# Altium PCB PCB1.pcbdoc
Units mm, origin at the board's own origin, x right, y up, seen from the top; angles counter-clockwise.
Board outline 149.48 x 93.01 mm, 2 copper layers (Top Layer, Bottom Layer); 121 components, 55 nets, 274 pads, 98 vias.
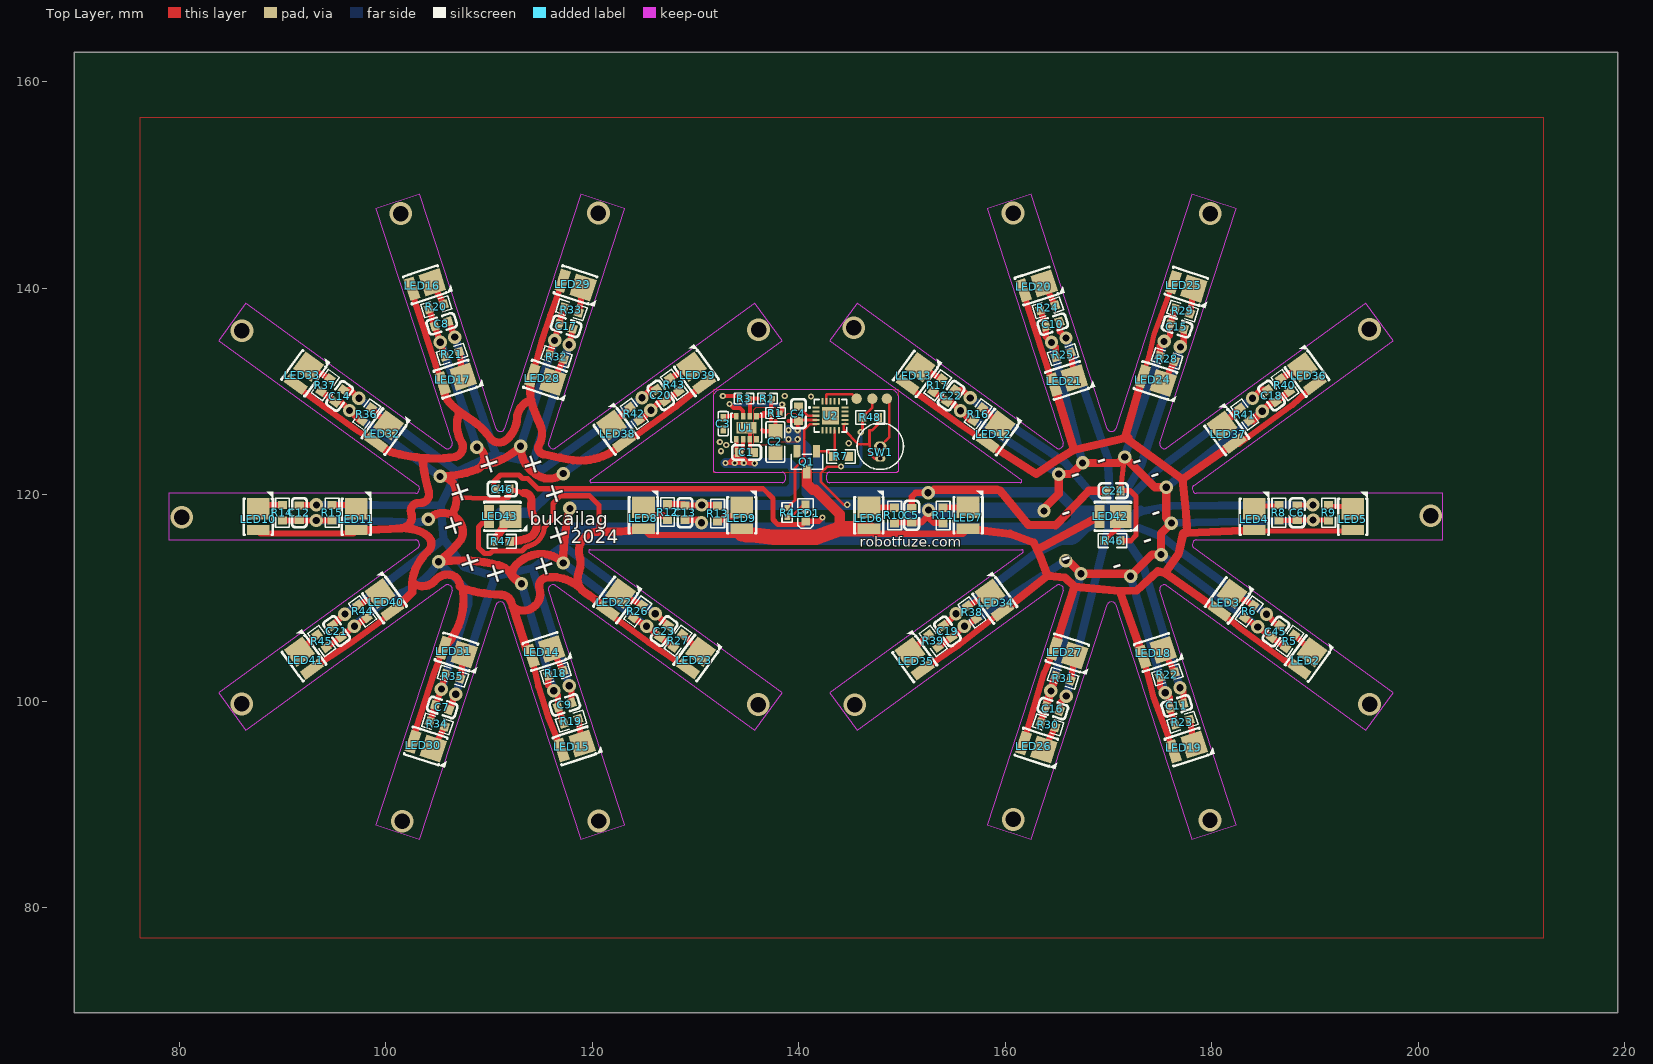
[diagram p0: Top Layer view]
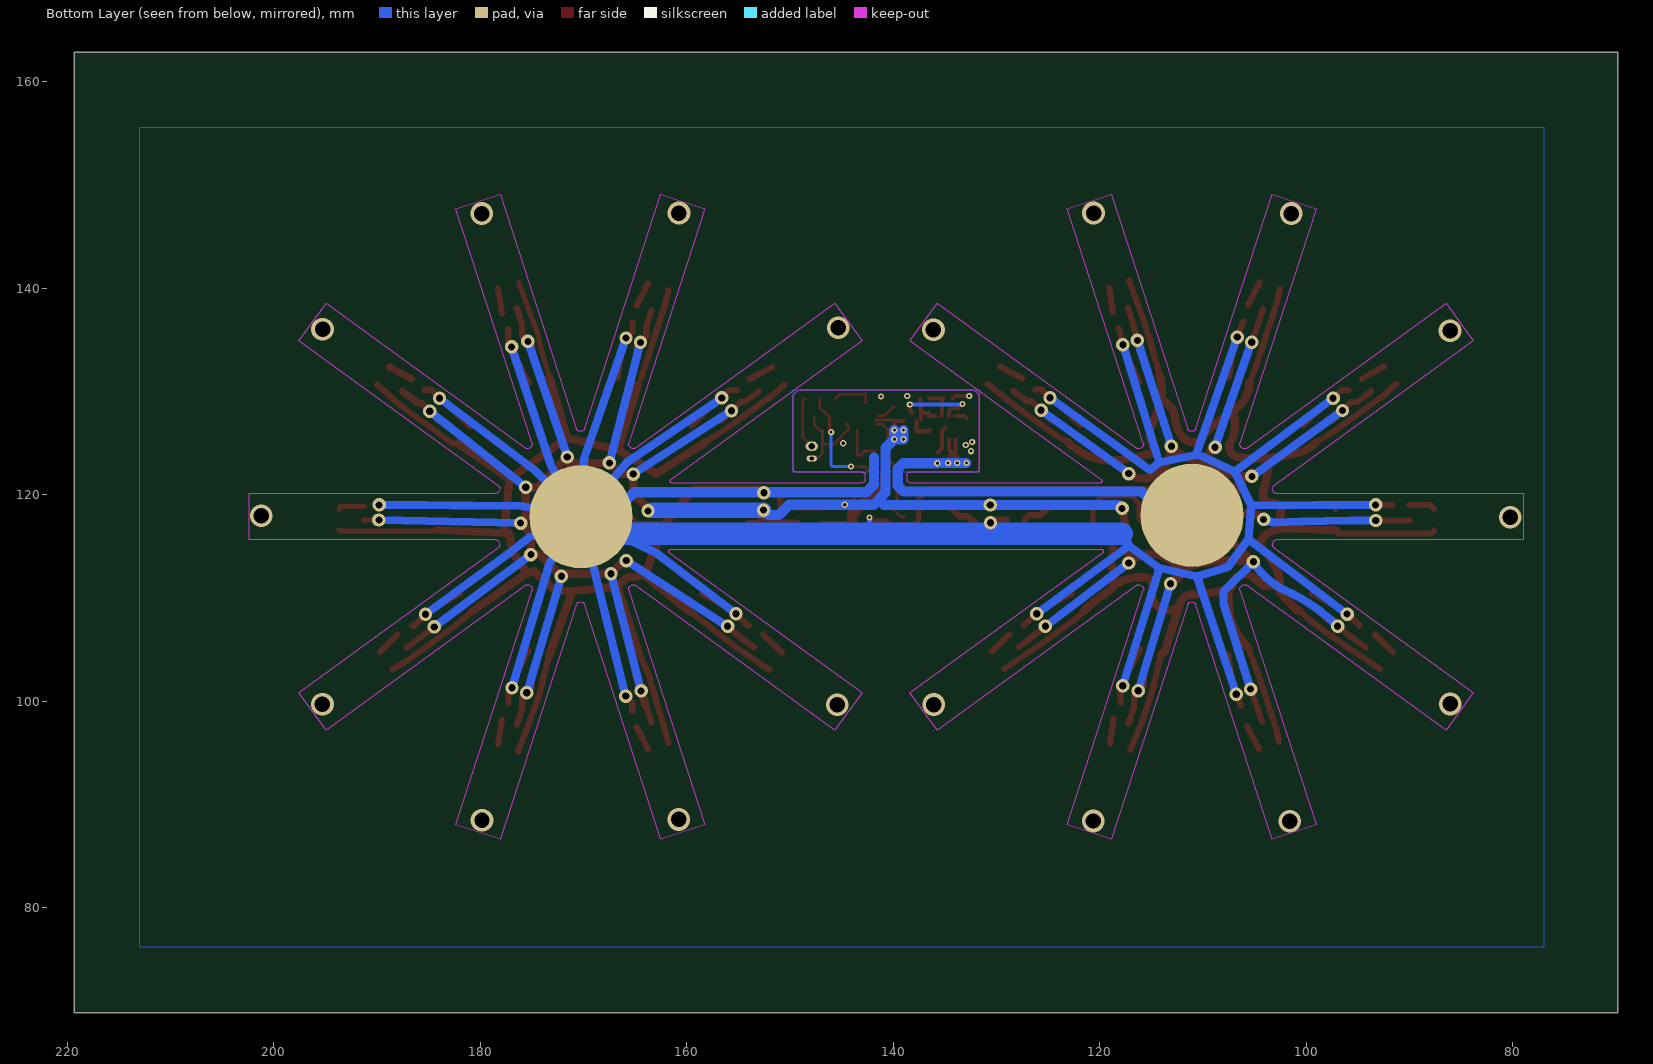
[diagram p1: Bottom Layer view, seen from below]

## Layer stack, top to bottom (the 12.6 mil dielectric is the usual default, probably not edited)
Top Layer: signal copper (thickness not stored)
Dielectric: dielectric 0.32, FR-4, Dk 4.8
Bottom Layer: signal copper (thickness not stored)

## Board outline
219.326,69.85 69.85,69.85 69.85,162.858 219.326,162.858

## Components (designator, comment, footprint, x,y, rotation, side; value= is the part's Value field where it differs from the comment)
C1 "GRM188R60J226MEA0D" C0603 134.95,124.111 r180 top
C2 "GRM21BR60J226ME39L" C0805 137.744,125.127 r90 top
C3 "430pF" C0402 132.702,126.905 r90 top
C4 "GRM188R60J226MEA0D" C0603 139.987,127.861 r270 top
C5 "GRM188R60J226MEA0D" C0603 150.952,118.015 r270 top
C6 "GRM188R60J226MEA0D" C0603 188.29,118.269 r270 top
C7 "GRM188R60J226MEA0D" C0603 105.475,99.41 r162 top
C8 "GRM188R60J226MEA0D" C0603 105.41,136.569 r198 top
C9 "GRM188R60J226MEA0D" C0603 117.348,99.651 r198 top
C10 "GRM188R60J226MEA0D" C0603 164.605,136.531 r198 top
C11 "GRM188R60J226MEA0D" C0603 176.606,99.562 r198 top
C12 "GRM188R60J226MEA0D" C0603 91.643,118.269 r270 top
C13 "GRM188R60J226MEA0D" C0603 128.994,118.281 r90 top
C14 "GRM188R60J226MEA0D" C0603 95.529,129.572 r234 top
C15 "GRM188R60J226MEA0D" C0603 176.644,136.29 r162 top
C16 "GRM188R60J226MEA0D" C0603 164.617,99.308 r162 top
C17 "GRM188R60J226MEA0D" C0603 117.471,136.327 r162 top
C18 "GRM188R60J226MEA0D" C0603 185.814,129.61 r306 top
C19 "GRM188R60J226MEA0D" C0603 154.419,106.775 r306 top
C20 "GRM188R60J226MEA0D" C0603 126.644,129.635 r306 top
C21 "GRM188R60J226MEA0D" C0603 95.25,106.801 r306 top
C22 "GRM188R60J226MEA0D" C0603 154.762,129.597 r234 top
C23 "GRM188R60J226MEA0D" C0603 126.962,106.801 r234 top
C24 "GRM188R60J226MEA0D" C0603 170.485,120.402 r0 top
C45 "GRM188R60J226MEA0D" C0603 186.22,106.763 r234 top
C46 "GRM188R60J226MEA0D" C0603 111.303,120.567 r0 top
LED1 "MHT192CRCT" LED0603-RD 140.678,118.243 r90 top
LED2 "L128-4080CB3500001_C358168" LED-SMD_L128-XX80CB3500001 189.118,103.931 r54 top
LED3 "L128-4080CB3500001_C358168" LED-SMD_L128-XX80CB3500001 181.371,109.572 r54 top
LED4 "L128-4080CB3500001_C358168" LED-SMD_L128-XX80CB3500001 184.142,117.628 r90 top
LED5 "L128-4080CB3500001_C358168" LED-SMD_L128-XX80CB3500001 193.665,117.628 r90 top
LED6 "L128-4080CB3500001_C358168" LED-SMD_L128-XX80CB3500001 146.808,117.755 r90 top
LED7 "L128-4080CB3500001_C358168" LED-SMD_L128-XX80CB3500001 156.413,117.761 r90 top
LED8 "L128-4080CB3500001_C358168" LED-SMD_L128-XX80CB3500001 124.968,117.755 r90 top
LED9 "L128-4080CB3500001_C358168" LED-SMD_L128-XX80CB3500001 134.491,117.755 r90 top
LED10 "L128-4080CB3500001_C358168" LED-SMD_L128-XX80CB3500001 87.662,117.628 r90 top
LED11 "L128-4080CB3500001_C358168" LED-SMD_L128-XX80CB3500001 97.157,117.628 r90 top
LED12 "L128-4080CB3500001_C358168" LED-SMD_L128-XX80CB3500001 158.912,125.876 r54 top
LED13 "L128-4080CB3500001_C358168" LED-SMD_L128-XX80CB3500001 151.152,131.517 r54 top
LED14 "L128-4080CB3500001_C358168" LED-SMD_L128-XX80CB3500001 115.113,104.743 r18 top
LED15 "L128-4080CB3500001_C358168" LED-SMD_L128-XX80CB3500001 118.034,95.612 r18 top
LED16 "L128-4080CB3500001_C358168" LED-SMD_L128-XX80CB3500001 103.54,140.27 r18 top
LED17 "L128-4080CB3500001_C358168" LED-SMD_L128-XX80CB3500001 106.511,131.128 r18 top
LED18 "L128-4080CB3500001_C358168" LED-SMD_L128-XX80CB3500001 174.342,104.655 r18 top
LED19 "L128-4080CB3500001_C358168" LED-SMD_L128-XX80CB3500001 177.314,95.488 r18 top
LED20 "L128-4080CB3500001_C358168" LED-SMD_L128-XX80CB3500001 162.785,140.145 r18 top
LED21 "L128-4080CB3500001_C358168" LED-SMD_L128-XX80CB3500001 165.732,131.006 r18 top
LED22 "L128-4080CB3500001_C358168" LED-SMD_L128-XX80CB3500001 122.118,109.608 r54 top
LED23 "L128-4080CB3500001_C358168" LED-SMD_L128-XX80CB3500001 129.883,103.981 r54 top
LED24 "L128-4080CB3500001_C358168" LED-SMD_L128-XX80CB3500001 174.315,131.156 r342 top
LED25 "L128-4080CB3500001_C358168" LED-SMD_L128-XX80CB3500001 177.299,140.289 r342 top
LED26 "L128-4080CB3500001_C358168" LED-SMD_L128-XX80CB3500001 162.77,95.642 r342 top
LED27 "L128-4080CB3500001_C358168" LED-SMD_L128-XX80CB3500001 165.768,104.763 r342 top
LED28 "L128-4080CB3500001_C358168" LED-SMD_L128-XX80CB3500001 115.183,131.275 r342 top
LED29 "L128-4080CB3500001_C358168" LED-SMD_L128-XX80CB3500001 118.13,140.421 r342 top
LED30 "L128-4080CB3500001_C358168" LED-SMD_L128-XX80CB3500001 103.632,95.764 r342 top
LED31 "L128-4080CB3500001_C358168" LED-SMD_L128-XX80CB3500001 106.611,104.869 r342 top
LED32 "L128-4080CB3500001_C358168" LED-SMD_L128-XX80CB3500001 99.675,125.914 r54 top
LED33 "L128-4080CB3500001_C358168" LED-SMD_L128-XX80CB3500001 91.902,131.568 r54 top
LED34 "L128-4080CB3500001_C358168" LED-SMD_L128-XX80CB3500001 159.149,109.566 r126 top
LED35 "L128-4080CB3500001_C358168" LED-SMD_L128-XX80CB3500001 151.402,103.903 r126 top
LED36 "L128-4080CB3500001_C358168" LED-SMD_L128-XX80CB3500001 189.395,131.528 r126 top
LED37 "L128-4080CB3500001_C358168" LED-SMD_L128-XX80CB3500001 181.628,125.858 r126 top
LED38 "L128-4080CB3500001_C358168" LED-SMD_L128-XX80CB3500001 122.479,125.927 r126 top
LED39 "L128-4080CB3500001_C358168" LED-SMD_L128-XX80CB3500001 130.251,131.578 r126 top
LED40 "L128-4080CB3500001_C358168" LED-SMD_L128-XX80CB3500001 100.051,109.607 r126 top
LED41 "L128-4080CB3500001_C358168" LED-SMD_L128-XX80CB3500001 92.245,103.968 r126 top
LED42 "L128-4080CB3500001_C358168" LED-SMD_L128-XX80CB3500001 170.18,117.913 r0 top
LED43 "L128-4080CB3500001_C358168" LED-SMD_L128-XX80CB3500001 111.052,117.912 r0 top
Q1 "AP3404" SOT-23-3_L2.9-W1.3-P1.90-LS2.4-BR-2 140.792,123.222 r180 top
R1 "CRCW0402100KFKED" R0402 137.744,127.921 r180 top
R2 "CRCW0402210KFKED" R0402 136.982,129.318 r0 top
R3 "CRCW0402100KFKED" R0402 134.709,129.318 r0 top
R4 "0402WGF1000TCE" R0402 138.887,118.292 r90 top
R5 "0603WAF100JT5E" R0603 187.592,105.835 r54 top
R6 "0603WAF100JT5E" R0603 183.642,108.706 r54 top
R7 "0603WAF100JT5E" R0603 144.094,123.73 r180 top
R8 "0603WAF100JT5E" R0603 186.512,118.269 r90 top
R9 "0603WAF100JT5E" R0603 191.338,118.269 r90 top
R10 "0603WAF100JT5E" R0603 149.301,118.015 r90 top
R11 "0603WAF100JT5E" R0603 154,118.015 r90 top
R12 "0603WAF100JT5E" R0603 127.305,118.332 r270 top
R13 "0603WAF100JT5E" R0603 132.156,118.193 r270 top
R14 "0603WAF100JT5E" R0603 89.992,118.269 r90 top
R15 "0603WAF100JT5E" R0603 94.818,118.269 r90 top
R16 "0603WAF100JT5E" R0603 157.378,127.806 r54 top
R17 "0603WAF100JT5E" R0603 153.466,130.615 r54 top
R18 "0603WAF100JT5E" R0603 116.472,102.711 r18 top
R19 "0603WAF100JT5E" R0603 117.958,98.076 r18 top
R20 "0603WAF100JT5E" R0603 104.902,138.22 r18 top
R21 "0603WAF100JT5E" R0603 106.413,133.623 r18 top
R22 "0603WAF100JT5E" R0603 175.717,102.572 r18 top
R23 "0603WAF100JT5E" R0603 177.178,97.987 r18 top
R24 "0603WAF100JT5E" R0603 164.134,138.113 r18 top
R25 "0603WAF100JT5E" R0603 165.621,133.56 r18 top
R26 "0603WAF100JT5E" R0603 124.422,108.706 r54 top
R27 "0603WAF100JT5E" R0603 128.321,105.874 r54 top
R28 "0603WAF100JT5E" R0603 175.692,133.204 r342 top
R29 "0603WAF100JT5E" R0603 177.19,137.814 r342 top
R30 "0603WAF100JT5E" R0603 164.158,97.725 r342 top
R31 "0603WAF100JT5E" R0603 165.621,102.241 r342 top
R32 "0603WAF100JT5E" R0603 116.548,133.382 r342 top
R33 "0603WAF100JT5E" R0603 117.996,137.916 r342 top
R34 "0603WAF100JT5E" R0603 105.004,97.809 r342 top
R35 "0603WAF100JT5E" R0603 106.512,102.431 r342 top
R36 "0603WAF100JT5E" R0603 98.171,127.794 r54 top
R37 "0603WAF100JT5E" R0603 94.17,130.639 r54 top
R38 "0603WAF100JT5E" R0603 156.794,108.617 r126 top
R39 "0603WAF100JT5E" R0603 153.043,105.846 r126 top
R40 "0603WAF100JT5E" R0603 187.109,130.639 r126 top
R41 "0603WAF100JT5E" R0603 183.197,127.781 r126 top
R42 "0603WAF100JT5E" R0603 124.092,127.845 r126 top
R43 "0603WAF100JT5E" R0603 127.953,130.677 r126 top
R44 "0603WAF100JT5E" R0603 97.76,108.713 r126 top
R45 "0603WAF100JT5E" R0603 93.802,105.835 r126 top
R46 "0603WAF100JT5E" R0603 170.409,115.564 r180 top
R47 "0603WAF100JT5E" R0603 111.252,115.5 r180 top
R48 "0603WAF100JT5E" R0603 146.93,127.507 r180 top
SW1 "SW-18010P" SW-TH_SW-18010P 147.904,124.111 r90 top
U1 "TPS82130SILR" USIP-8_L3.0-W2.8-P0.65-TL-EP 134.949,126.502 r90 top
U2 "ATTINY1616-MNR" QFN-20_L3.0-W3.0-P0.40-BL-EP1.7 143.093,127.665 r270 top

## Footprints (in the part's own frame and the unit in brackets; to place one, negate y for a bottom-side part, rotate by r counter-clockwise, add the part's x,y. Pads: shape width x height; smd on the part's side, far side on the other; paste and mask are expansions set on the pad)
C0402 [mm]
  rect 0.79x0.54 smd: 1(-0.545,0) 2(0.545,0)
  silkscreen extent -1.17,-0.5 1.17,0.5
C0603 [mm]
  rect 0.8x0.9 smd: 1(-0.7,0) 2(0.7,0)
  silkscreen extent -1.41,-0.71 1.39,0.72
C0805 [mm]
  rect 1.41x1.35 smd: 1(-1.03,0) 2(1.03,0)
  silkscreen extent -1.96,-0.9 1.96,0.9
LED0603-RD [mm]
  rect 0.8x0.8 smd: 1(-0.799,-0.003) 2(0.799,0.003)
  silkscreen extent -1.49,-0.75 1.39,0.76
LED-SMD_L128-XX80CB3500001 [mm]
  rect 1x2.2 smd: 1(-1.035,0)
  rect 2.1x2.2 smd: 2(1.035,0)
  silkscreen extent -1.49,-1.45 2.66,1.4
QFN-20_L3.0-W3.0-P0.40-BL-EP1.7 [mm]
  rect 0.2x0.665 smd: 1(-0.8,-1.407) 2(-0.4,-1.407) 3(0,-1.407) 4(0.4,-1.407) 5(0.8,-1.407) 11(0.8,1.407) 12(0.4,1.407) 13(0,1.407) 14(-0.4,1.407) 15(-0.8,1.407)
  rect 0.665x0.2 smd: 6(1.407,-0.8) 7(1.407,-0.4) 8(1.407,0) 9(1.407,0.4) 10(1.407,0.8) 16(-1.407,0.8) 17(-1.407,0.4) 18(-1.407,0) 19(-1.407,-0.4) 20(-1.407,-0.8)
  rect 1.65x1.65 smd: 21(0,0)
  silkscreen extent -1.58,-2.11 1.58,1.58
R0402 [mm]
  rect 0.566x0.54 smd: 1(-0.433,0) 2(0.433,0)
  silkscreen extent -0.94,-0.5 0.94,0.5
R0603 [mm]
  rect 0.806x0.864 smd: 1(-0.753,0) 2(0.753,0)
  silkscreen extent -1.39,-0.66 1.39,0.66
SOT-23-3_L2.9-W1.3-P1.90-LS2.4-BR-2 [mm]
  rect 0.7x1.25 smd: 1(0.95,-1) 2(-0.95,-1) 3(0,1)
  silkscreen extent -1.53,-0.73 1.53,0.73
SW-TH_SW-18010P [mm]
  oval 0.9x1.2 hole 0.6: 1(0.6,0)
  oval 0.6x1 hole 0.4: 2(-0.6,0)
  silkscreen extent -1.65,-2.25 2.85,2.25
USIP-8_L3.0-W2.8-P0.65-TL-EP [mm]
  rect 0.65x0.45 smd: 1(-1.125,0.975) 2(-1.125,0.325) 3(-1.125,-0.325) 4(-1.125,-0.975) 5(1.125,-0.975) 6(1.125,-0.325) 7(1.125,0.325) 8(1.125,0.975)
  rect 1.1x1.9 smd: 9(0,0)
  silkscreen extent -1.73,-1.5 1.4,1.5

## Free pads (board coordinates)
  round 1 smd: 4(145.618,129.318) 6(147.142,129.318) 7(148.539,129.318)
  round 10 smd far side: 5(111.074,118.015) 5(170.256,117.888)

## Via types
v1: diameter 1.3, hole 0.7, Top Layer to Bottom Layer, 59 vias
v2: diameter 0.61, hole 0.305, Top Layer to Bottom Layer, 21 vias
v3: diameter 2.2, hole 1.5, Top Layer to Bottom Layer, 18 vias

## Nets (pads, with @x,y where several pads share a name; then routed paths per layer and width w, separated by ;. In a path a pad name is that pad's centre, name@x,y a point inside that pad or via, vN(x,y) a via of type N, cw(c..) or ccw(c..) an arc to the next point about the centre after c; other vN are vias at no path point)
2.5V: C2.2 C4.2 C5.2 C6.2 C7.2 C8.2 C9.2 C10.2 C11.2 C12.2 C13.2 C14.2 C15.2 C16.2 C17.2 C18.2 C19.2 C20.2 C21.2 C22.2 C23.2 C24.2 C45.2 C46.2 pad.6 R1.2 R2.2 R5.1 R6.1 R8.1 R9.1 R10.1 R11.1 R12.1 R13.1 R14.1 R15.1 R16.1 R17.1 R18.1 R19.1 R20.1 R21.1 R22.1 R23.1 R24.1 R25.1 R26.1 R27.1 R28.1 R29.1 R30.1 R31.1 R32.1 R33.1 R34.1 R35.1 R36.1 R37.1 R38.1 R39.1 R40.1 R41.1 R42.1 R43.1 R44.1 R45.1 R46.1 R47.1 R48.2 U1.4 U1.5 U2.4 | length 497.5
  Top Layer w0.25: C4.2@140.035,127.113 140.175,127.252 141.219,127.252 U2.4@141.711,127.252 ; v2(144.094,122.739) 142.773,122.739 142.13,122.095 142.13,121.313 144.412,119.031 v2@144.666,119.031 ; R48.2@146.253,127.583 147.142,128.473 pad.6
  Top Layer w0.3: v2(146.025,126.079) 146.176,126.231 R48.2 R48.2@146.253,127.583
  Top Layer w0.4: U1.5 136.561,127.627 136.601,127.667 ; 136.474,126.27 136.587,126.157 C2.2 137.744,127.159 ; 136.601,127.921 R1.2 ; 137.311,127.286 R1.2 ; R2.2 137.363,129.266 137.363,128.81 137.311,128.758 R1.2 ; 139.014,127.161 C4.2 140.035,127.113 139.903,126.981 v2(139.903,126.27)
  Top Layer w0.5: 106.881,119.744 111.239,119.59 111.9,119.729 C46.2 113.36,120.186 ; R46.1 172.161,115.564 172.682,116.084 172.682,119.844 172.098,120.428 171.21,120.428 C24.2 v1(171.577,123.666) ; R8.1@186.385,117.515 188.237,117.515 C6.2 v1(189.826,117.569) 191.285,117.569 R9.1
  Top Layer w0.6: R14.1 91.59,117.515 C12.2 91.692,117.519 v1(93.269,117.519) 94.814,117.519 R15.1 ; R37.1 C14.2 95.664,129.005 v1(96.495,128.175) 97.485,127.184 R36.1 ; R45.1 C21.2 v1(96.977,107.283) R44.1 ; R20.1 C8.2 v1(105.296,134.791) R21.1 ; R34.1 C7.2 v1(105.397,101.187) R35.1 ; R18.1 115.755,101.548 v1(116.281,101.022) 116.682,100.621 C9.2 R19.1 ; R32.1 v1(116.357,134.957) C17.2 R33.1 ; R26.1 v1(125.273,107.283) C23.2 R27.1 ; R42.1 124.74,127.235 v1(125.692,128.187) 126.573,129.069 C20.2 R43.1 ; R12.1 128.89,119.086 C13.2 130.583,118.981 v1(130.619,119.018) 132.084,119.018 R13.1 ; R10.1 149.355,117.315 C5.2 151.89,117.315 v1@152.578,118.002 ; v1(152.578,118.523) v1@152.578,118.002 ; R17.1 C22.2 154.795,129.031 v1(155.677,128.149) 156.629,127.197 R16.1 ; R39.1 C19.2 v1(156.058,107.271) R38.1 ; R11.1 153.115,117.261 152.578,117.799 v1@152.578,118.002 ; R24.1 C10.2 163.939,135.318 v1(164.49,134.766) 164.904,134.352 R25.1 ; R30.1 C16.2 ; R28.1 174.975,134.443 v1(175.4,134.868) 175.979,135.446 C15.2 R29.1 ; R22.1 175.001,101.345 v1(175.501,100.844) 175.94,100.405 C11.2 R23.1 ; R6.1 v1(184.48,107.207) C45.2 R5.1
  Top Layer w0.7: R41.1 183.985,127.172 v1(184.912,128.099) 185.714,128.9 186.082,128.9 C18.2 R40.1
  Top Layer w0.8: v1@104.14,117.621 cw(c105.568,116.315) 106.404,118.06 ; v1(108.839,124.619) cw(c108.42,123.549) 109.329,122.847 ; R47.1 ccw(c112.005,120.815) 113.779,115.805 ccw(c113.364,116.979) 114.452,117.583 cw(c116.935,118.961) 114.122,119.348 ccw(c113.391,119.449) 113.36,120.186 ; v1(117.196,122.066) cw(c115.835,123.7) 114.935,121.774 cw(c116.307,124.708) v1(113.068,124.708) cw(c108.424,129.351) 109.329,122.847 ; v1@117.843,118.688 ccw(c139.067,113.405) 117.196,113.405 ccw(c115.075,111.284) 114.452,114.217 ccw(c115.193,110.73) 112.725,113.303 ccw(c113.875,112.105) 112.216,112.184 ; v1(163.766,118.447) 163.766,118.662 165.189,120.085 v1(165.189,122.015) 166.421,122.015 v1(167.5,123.095) 171.005,123.095 v1(171.577,123.666) 174.511,120.733 v1(175.603,120.733) 175.603,117.773 v1(176.111,117.265) 175.108,116.262 v1(175.108,114.217) 174.244,114.217 v1(172.148,112.122) 171.907,112.363 v1(167.348,112.363) 166.078,113.633 v1(165.862,113.633) ; C16.2 v1(164.44,101.009) R31.1 ; 106.404,118.06 cw(c105.568,116.315) 106.909,117.71 cw(c105.784,116.445) 107.252,115.602 cw(c96.944,123.977) 105.131,113.519 cw(c107.292,95.607) 108.839,113.582 cw(c106.681,96.585) 110.96,113.176 cw(c110.465,111.258) 112.216,112.184 ; 106.404,118.06 ccw(c103.51,119.791) 106.881,119.744 ccw(c103.51,119.791) 106.782,120.606 ccw(c105.27,120.229) v1(105.27,121.787) ccw(c105.27,131.317) 108.852,122.485 ccw(c108.42,123.549) 109.329,122.847 ; 112.216,112.184 cw(c110.591,109.317) v1(113.157,111.385) cw(c114.425,113.833) 112.216,112.184
  Bottom Layer w0.3: v2(144.094,122.739) 145.859,122.739 146.025,122.904 v2(146.025,126.079)
  Bottom Layer w0.8: v1(93.269,117.519) cw(c93.269,-136.476) 102.995,117.333 ccw(c102.88,120.211) v1(104.14,117.621) ; v1(96.495,128.175) v1(105.27,121.787) ; v1(96.977,107.283) cw(c108.601,95.66) 102.083,110.75 ccw(c98.92,117.294) v1(105.131,113.519) 108.013,110.636 108.013,109.468 v1(105.397,101.187) ; v1(105.296,134.791) v1(108.839,124.619) ; v1(113.068,124.708) v1(116.357,134.957) ; v1(113.157,111.385) v1(116.281,101.022) ; v1(117.196,113.405) v1(125.273,107.283) ; v1(117.196,122.066) v1(125.692,128.187) ; v1(155.677,128.149) v1(165.189,122.015) ; v1(156.058,107.271) v1(165.862,113.633) ; v1(164.44,101.009) v1(167.348,112.363) ; v1(164.49,134.766) v1(167.5,123.095) ; v1(171.577,123.666) v1(175.4,134.868) ; v1(172.148,112.122) v1(175.501,100.844) ; v1(175.108,114.217) v1(184.48,107.207) ; v1(175.603,120.733) v1(184.912,128.099) ; v1(176.111,117.265) v1(189.826,117.569)
  Bottom Layer w1: v1(117.843,118.688) 118.173,119.018 v1(130.619,119.018) 140.894,119.018 141.262,119.386 ; v2(139.014,126.27) v2(139.014,125.381) v2(139.903,125.381) ; v2(139.903,126.27) v2(139.903,125.381) ; v1(152.578,118.523) 152.098,118.043 151.089,118.043 150.089,119.043 v2(144.708,119.043) 141.91,119.043 140.767,120.186 140.767,124.517 v2(139.903,125.381)
  Bottom Layer w1.5: v1(152.578,118.523) v1@163.411,118.523
$1N1273: R1.1 U1.7 | length 8.2
  Top Layer w0.4: v2(133.299,128.81) 133.68,128.429 134.315,128.429 134.624,128.12 U1.7 ; R1.1 138.402,128.146 v2(138.402,128.758)
  Bottom Layer w0.4: v2(133.299,128.81) 133.351,128.758 v2(138.402,128.758)
$1N1291: C3.2 U1.8 | length 1.1
  Top Layer w0.4: C3.2@132.918,127.45 133.095,127.627 U1.8
$1N1523: R2.1 R3.2 U1.6 | length 3.2
  Top Layer w0.4: U1.6 135.274,129.173 135.129,129.318 R2.1
$1N2150: R4.2 U2.5 | length 9.6
  Top Layer w0.25: R4.2 139.649,119.487 139.649,122.587 140.538,123.476 140.538,126.27 141.122,126.854 U2.5@141.712,126.854
$1N2153: LED1.2 R4.1 | length 2.3
  Top Layer w0.25: R4.1 139.282,117.859 140.491,119.068 LED1.2@140.662,119.068
$1N2397: LED2.2 R5.2 | length 2.4
  Top Layer w0.6: R5.2 LED2.2
$1N2467: LED3.2 R6.2 | length 2.4
  Top Layer w0.6: LED3.2 R6.2
$1N2959: LED4.2 R8.2 | length 2.3
  Top Layer w0.5: LED4.2@184.142,118.917 186.363,118.917 186.385,118.939 R8.2@186.385,119.022
$1N2961: LED5.2 R9.2 | length 2.4
  Top Layer w0.5: R9.2@191.252,118.873 LED5.2@193.621,118.873 ; LED5.2@193.621,118.619 LED5.2
$1N3108: LED6.2 R10.2 | length 2.5
  Top Layer w0.6: LED6.2 146.829,118.768 R10.2
$1N3110: LED7.2 R11.2 | length 2.4
  Top Layer w0.6: R11.2 156.386,118.768 LED7.2
$1N3257: LED8.2 R12.2 | length 2.8
  Top Layer w0.6: LED8.2 125.73,118.027 126.856,118.027 R12.2
$1N3259: LED9.2 R13.2 | length 2.9
  Top Layer w0.6: R13.2 132.355,117.439 132.855,117.939 133.639,117.939 LED9.2
$1N3406: LED10.2 R14.2 | length 2.5
  Top Layer w0.6: LED10.2 88.021,119.022 R14.2
$1N3408: LED11.2 R15.2 | length 2.5
  Top Layer w0.6: R15.2 96.797,119.022 LED11.2
$1N4472: LED12.2 R16.2 | length 2.4
  Top Layer w0.6: R16.2 LED12.2
$1N4474: LED13.2 R17.2 | length 2.4
  Top Layer w0.6: LED13.2 R17.2
$1N4476: LED14.2 R18.2 | length 2.4
  Top Layer w0.6: LED14.2 R18.2
$1N4478: LED15.2 R19.2 | length 2.4
  Top Layer w0.6: R19.2 LED15.2
$1N4480: LED16.2 R20.2 | length 2.4
  Top Layer w0.6: LED16.2 R20.2
$1N4482: LED17.2 R21.2 | length 2.4
  Top Layer w0.6: R21.2 LED17.2
$1N4484: LED18.2 R22.2 | length 2.4
  Top Layer w0.6: LED18.2 R22.2
$1N4486: LED19.2 R23.2 | length 2.4
  Top Layer w0.6: R23.2 LED19.2
$1N4488: LED20.2 R24.2 | length 2.4
  Top Layer w0.6: LED20.2 R24.2
$1N4490: LED21.2 R25.2 | length 2.5
  Top Layer w0.6: R25.2 LED21.2
$1N5215: LED22.2 R26.2 | length 2.4
  Top Layer w0.6: LED22.2 R26.2
$1N5217: LED23.2 R27.2 | length 2.4
  Top Layer w0.6: R27.2 LED23.2
$1N5219: LED24.2 R28.2 | length 2.4
  Top Layer w0.6: LED24.2 R28.2
$1N5221: LED25.2 R29.2 | length 2.4
  Top Layer w0.6: R29.2 LED25.2
$1N5223: LED26.2 R30.2 | length 2.4
  Top Layer w0.6: LED26.2 R30.2
$1N5225: LED27.2 R31.2 | length 2.5
  Top Layer w0.6: R31.2 LED27.2
$1N5227: LED28.2 R32.2 | length 2.5
  Top Layer w0.6: LED28.2 R32.2
$1N5229: LED29.2 R33.2 | length 2.5
  Top Layer w0.6: R33.2 LED29.2
$1N5231: LED30.2 R34.2 | length 2.4
  Top Layer w0.6: LED30.2 R34.2
$1N5233: LED31.2 R35.2 | length 2.4
  Top Layer w0.6: R35.2 LED31.2
$1N5958: LED32.2 R36.2 | length 2.3
  Top Layer w0.6: R36.2 LED32.2
$1N5960: LED33.2 R37.2 | length 2.4
  Top Layer w0.6: LED33.2 R37.2
$1N5962: LED34.2 R38.2 | length 2.5
  Top Layer w0.6: R38.2 LED34.2
$1N5964: LED35.2 R39.2 | length 2.5
  Top Layer w0.6: LED35.2 R39.2
$1N5966: LED36.2 R40.2 | length 2.4
  Top Layer w0.7: R40.2 LED36.2
$1N5968: LED37.2 R41.2 | length 2.4
  Top Layer w0.7: LED37.2 R41.2
$1N5970: LED38.2 R42.2 | length 2.5
  Top Layer w0.6: LED38.2 R42.2
$1N5972: LED39.2 R43.2 | length 2.4
  Top Layer w0.6: R43.2 LED39.2
$1N5974: LED40.2 R44.2 | length 2.4
  Top Layer w0.6: R44.2 LED40.2
$1N5976: LED41.2 R45.2 | length 2.4
  Top Layer w0.6: LED41.2 R45.2
$1N6160: LED42.2 R46.2 | length 3
  Top Layer w0.5: R46.2 171.215,117.123 LED42.2
$1N6162: LED43.2 R47.2 | length 2.9
  Top Layer w0.8: R47.2 LED43.2
BAT_+: C1.2 pad.5@111.074,118.015 U1.1 U1.2 | length 49.7
  Top Layer w0.4: v2(132.918,123.095) 133.234,123.095 ; U1.1 133.974,124.174 C1.2@134.143,124.004 ; U1.2 134.624,124.375 C1.2@134.274,124.025 ; 133.234,123.095 C1.2@134.143,124.004 ; 133.234,123.095 v2(133.807,123.095) ; v2(133.807,123.095) v2(134.696,123.095) ; v2(133.807,123.095) 134.25,123.538 134.25,123.541 ; C1.2@134.143,124.004 C1.2 C1.2@134.25,124.049 ; C1.2@134.143,124.004 134.198,123.949 C1.2@134.25,124.001 ; 134.25,123.541 v2(134.696,123.095) ; 134.25,123.541 C1.2@134.25,124.001 ; C1.2@134.25,124.001 C1.2@134.25,124.049 ; C1.2@134.25,124.001 C1.2@134.274,124.025 ; C1.2@134.25,124.049 C1.2@134.274,124.025 ; C1.2@134.274,124.025 135.204,123.095 ; v2(134.696,123.095) 135.204,123.095 ; 135.204,123.095 135.242,123.057 v2(135.738,123.057) 135.7,123.095 135.204,123.095
  Bottom Layer w0.127: pad.5@111.074,118.269 111.328,118.015 pad.5@111.328,117.888
  Bottom Layer w1: pad.5@111.074,118.269 113.868,118.269 115.92,120.32 139.009,120.32 139.586,120.898 139.586,122.536 139.065,123.057 v2(135.738,123.057) 135.7,123.095 v2(134.696,123.095) v2(133.807,123.095) v2(132.918,123.095)
GND: C1.1 C2.1 C3.1 C4.1 C5.1 C6.1 C7.1 C8.1 C9.1 C10.1 C11.1 C12.1 C13.1 C14.1 C15.1 C16.1 C17.1 C18.1 C19.1 C20.1 C21.1 C22.1 C23.1 C24.1 C45.1 C46.1 LED1.1 pad.5@170.256,117.888 pad.7 Q1.1 R3.1 R7.1 SW1.1 U1.3 U1.9 U2.3 | length 488.3
  Top Layer w0.25: C4.1 140.881,127.667 U2.3@141.417,127.667 ; SW1.1 148.793,125.6 148.793,129.064 pad.7
  Top Layer w0.4: v2(132.664,129.572) 134.009,129.572 R3.1@134.263,129.318 ; U1.9 135.274,126.177 U1.3 135.274,124.487 C1.1
  Top Layer w0.5: C46.1@110.501,120.44 110.501,121.315 111.125,121.939 112.903,121.939 113.259,121.583 113.759,121.583 114.749,120.593 136.563,120.593 137.503,119.653 137.503,117.608 137.986,117.126 140.363,117.126 LED1.1 141.961,117.444 v2(142.316,117.799) ; C6.1 188.352,119.031 v1(189.814,119.031)
  Top Layer w0.6: C12.1 91.705,119.031 v1(93.294,119.031) ; C21.1 v1(96.05,108.452) ; C14.1 96.627,130.138 v1(97.409,129.356) ; C8.1 v1(106.693,135.287) ; C7.1@106.345,99.559 106.713,100.652 v1(106.794,100.692) ; v1(117.767,134.537) C17.1 ; v1(117.78,101.517) 118.014,101.283 C9.1 ; v1(124.828,129.407) 125.623,130.202 C20.1 ; v1(126.111,108.477) C23.1 ; C13.1 130.304,117.581 v1(130.594,117.291) ; C5.1 150.952,119.818 151.333,120.199 v1(152.54,120.199) ; C19.1 154.109,107.342 v1(155.245,108.477) ; C22.1 155.847,130.163 v1(156.616,129.394) ; C10.1 165.27,135.827 v1(165.9,135.198) ; C16.1 165.283,99.872 v1(165.925,100.514) ; v1(176.936,101.327) 177.272,100.991 C11.1 ; v1(176.975,134.334) 177.31,134.67 C15.1 ; v1(183.959,129.356) 184.78,130.176 C18.1 ; v1(185.318,108.426) 186.416,107.329 C45.1
  Top Layer w0.8: v1@153.111,120.488 159.232,120.488 159.537,120.402 162.243,117.088 164.884,117.05 168.11,120.402 C24.1
  Bottom Layer w0.5: 142.304,116.237 142.316,116.249 v2(142.316,117.799)
  Bottom Layer w0.8: v1(93.294,119.031) 105.346,118.98 ; v1(96.05,108.452) 105.283,115.449 105.613,115.729 ; v1(97.409,129.356) 106.921,122.257 ; v1(106.693,135.287) 110.693,123.869 114.249,123.146 ; v1(106.794,100.692) 110.579,112.109 ; 110.426,123.908 106.921,122.257 ; v1(117.767,134.537) 114.249,123.146 ; v1(117.78,101.517) 114.224,112.897 ; 117.894,116.491 117.17,115.081 ; v1(124.828,129.407) 115.138,122.409 114.249,123.146 ; v1(126.111,108.477) 117.17,115.081 ; v1(155.245,108.477) 162.852,114.281 pad.5@170.256,117.888 ; v1(156.616,129.394) 165.887,123.069 pad.5@170.256,117.888 ; v1(165.9,135.198) 169.939,123.552 pad.5@170.256,117.888 ; v1(165.925,100.514) pad.5@170.256,117.888 ; pad.5@172.858,118.356 176.047,118.929 v1(189.814,119.031) ; v1(176.936,101.327) 173.304,113.341 pad.5@170.256,117.888 ; v1(176.975,134.334) 173.152,122.828 pad.5@170.256,117.888 ; v1(183.959,129.356) 174.803,122.434 pad.5@170.256,117.888 ; v1(185.318,108.426) 176.987,114.522 175.26,115.894 pad.5@170.256,117.888 ; 105.346,118.98 106.921,122.257 ; 105.346,118.98 105.613,115.729 ; 105.613,115.729 107.594,113.024 110.579,112.109 ; 110.579,112.109 114.224,112.897 ; 114.224,112.897 117.17,115.081
  Bottom Layer w1: 141.869,123.599 141.869,121.025 142.632,120.262 v1@152.594,120.262 ; v1(152.54,120.199) 152.54,120.207 v1@152.594,120.262 ; pad.5@167.462,117.888 165.088,120.262 v1@152.594,120.262 ; pad.5@170.256,117.888 172.39,117.888 pad.5@172.858,118.356 ; pad.5@172.96,118.458 173.074,118.458 173.105,118.488 pad.5@172.96,118.458
  Bottom Layer w2.2: 117.869,116.237 142.304,116.237 166.37,116.237 167.462,117.329 167.462,117.888 pad.5@170.256,117.888
  other v2: 132.474,124.238 132.982,124.835 144.856,125 132.372,125.127 141.199,129.534 138.659,129.572
  other v3: 101.613,88.386 120.65,88.411 179.845,88.487 160.795,88.563 145.428,99.663 136.081,99.689 195.301,99.727 86.068,99.752 80.239,117.837 201.231,117.977 86.081,135.884 136.119,135.998 195.288,136.049 145.351,136.176 101.448,147.25 179.883,147.25 120.612,147.301 160.769,147.301
MOSFET: Q1.2 R7.2 U2.9 | length 4.4
  Top Layer w0.25: Q1.2 142.849,124.222 R7.2 143.493,123.882 U2.9
SWITCH: LED2.1 LED3.1 LED4.1 LED5.1 LED6.1 LED7.1 LED8.1 LED9.1 LED10.1 LED11.1 LED12.1 LED13.1 LED14.1 LED15.1 LED16.1 LED17.1 LED18.1 LED19.1 LED20.1 LED21.1 LED22.1 LED23.1 LED24.1 LED25.1 LED26.1 LED27.1 LED28.1 LED29.1 LED30.1 LED31.1 LED32.1 LED33.1 LED34.1 LED35.1 LED36.1 LED37.1 LED38.1 LED39.1 LED40.1 LED41.1 LED42.1 LED43.1 Q1.3 | length 459.4
  Top Layer w0.5: LED43.1 109.004,116.899 109.004,114.878 109.563,114.319 110.109,114.319 110.363,114.573 113.208,114.573 113.595,114.96 ccw(c112.005,120.815) 114.03,115.096 ccw(c113.364,116.979) 115.357,116.849 116.205,117.698 116.205,119.158 116.967,119.92 119.748,119.92 120.675,118.993 120.675,116.44 ; LED24.1 174.015,133.788 174.422,135.541 LED25.1 ; LED4.1 184.244,116.491 193.562,116.491 LED5.1
  Top Layer w0.6: LED10.1@87.649,116.517 87.896,116.27 96.897,116.27 LED11.1@97.144,116.517 ; LED33.1 92.515,129.641 97.068,126.333 LED32.1 ; LED41.1 96.506,105.573 99.64,107.85 LED40.1 ; LED16.1 102.854,138.657 104.857,132.49 LED17.1 ; LED30.1 102.911,97.294 104.676,102.726 LED31.1 ; LED14.1 114.784,101.44 115.731,98.525 LED15.1 ; LED28.1 115.158,134.987 115.943,137.403 LED29.1 ; LED22.1 122.35,107.965 125.538,105.648 LED23.1 ; LED38.1 124.396,125.836 128.088,128.519 LED39.1 ; LED8.1 125.578,116.11 133.88,116.11 LED9.1 ; LED6.1 147.291,116.237 155.924,116.237 LED7.1 ; LED13.1 151.715,129.645 155.814,126.667 LED12.1 ; LED35.1 155.137,105.158 155.406,105.353 LED34.1 ; LED26.1 163.782,102.781 LED27.1 ; LED20.1 162.235,138.105 LED21.1@164.452,131.282 ; LED18.1 174.361,100.398 LED19.1 ; LED3.1 182.793,107.063 186.99,104.014 LED2.1 ; LED37.1 182.632,124.935 187.867,128.738 LED36.1
  Top Layer w0.8: LED11.1 ccw(c97.157,170.457) 101.524,116.77 ccw(c101.434,117.869) 102.476,118.231 cw(c103.175,118.473) 103.251,119.209 ccw(c103.34,120.072) 104.178,120.301 cw(c125.614,126.144) 103.544,123.581 ; LED32.1 ccw(c101.819,127.83) 100.8,124.073 ccw(c104.972,139.454) 103.544,123.581 ; LED40.1 100.792,108.77 102.565,110.543 ccw(c100.63,110.712) 102.565,110.877 cw(c106.474,111.21) 102.561,111.492 ; 102.019,116.732 cw(c102.019,113.437) 104.064,116.021 cw(c103.469,115.269) 104.127,114.573 ccw(c107.811,110.676) 102.832,112.668 ccw(c106.474,111.21) 102.561,111.492 ; LED17.1 ccw(c108.485,130.808) 106.553,128.568 ccw(c115.824,139.316) 107.175,128.062 ; LED31.1 ccw(c101.009,109.806) 107.437,110.957 ccw(c111.409,123.091) 111.137,110.326 cw(c111.105,108.827) 111.324,110.311 cw(c111.171,109.272) 112.169,109.596 112.319,109.137 ; 107.188,111.157 ccw(c106.065,111.157) 106.172,112.274 ccw(c106.021,110.687) 104.813,111.728 cw(c103.561,112.807) 102.561,111.492 ; LED14.1 cw(c118.443,108.738) 113.692,104.909 112.319,109.137 ; LED28.1 ccw(c119.136,130.163) 114.091,129.175 ; LED22.1 ccw(c112.27,99.531) 119.317,110.534 cw(c120.173,111.872) 118.94,110.871 ; LED38.1 cw(c118.837,129.34) 117.767,123.425 cw(c126.819,173.469) 115.253,123.946 cw(c115.393,124.548) 114.859,124.86 ccw(c113.027,125.929) 114.948,126.829 cw(c130.14,133.943) 114.275,128.492 cw(c119.136,130.163) 114.091,129.175 ; LED8.1 cw(c121.616,135.063) 120.675,116.44 ccw(c120.581,114.579) 118.783,114.09 cw(c116.262,113.406) 118.694,112.452 ccw(c120.173,111.872) 118.94,110.871 ; LED7.1 160.477,116.224 162.789,115.36 163.098,114.682 ; LED12.1 163.017,122.028 165.176,123.488 166.675,124.365 ; LED34.1 164.097,112.16 ; LED21.1 166.675,124.365 ; LED27.1 166.713,111.106 ; LED42.1 163.098,114.682 ; 171.933,125.559 171.661,125.497 ; LED24.1 171.628,125.52 171.661,125.497 ; LED18.1 171.107,110.7 ; LED3.1 175.501,112.439 ; LED37.1 177.19,121.507 ; LED4.1 177.64,116.305 ; 103.544,123.581 ccw(c104.972,139.454) 104.127,123.539 ccw(c104.773,135.708) 106.642,123.666 ccw(c106.491,124.64) 107.34,125.139 cw(c110.1,126.761) 107.175,128.062 ; 107.175,128.062 ccw(c115.824,139.316) 108.191,127.349 cw(c104.472,121.517) 110.122,125.508 ccw(c110.981,126.115) 111.62,125.279 ccw(c109.925,127.494) 112.712,127.387 cw(c114.658,127.313) 114.091,129.175 ; 112.319,109.137 ccw(c113.327,110.437) 114.897,110.928 cw(c115.687,111.175) 115.57,111.995 cw(c116.131,108.062) 118.94,110.871 ; 163.098,114.682 163.449,113.913 164.097,112.16 ; 164.097,112.16 165.798,112.008 166.713,111.106 ; 166.675,124.365 171.661,125.497 ; 166.713,111.106 171.107,110.7 ; 171.107,110.7 172.758,110.738 174.777,112.605 175.501,112.439 ; 171.661,125.497 177.19,121.507 ; 175.501,112.439 176.784,114.256 177.254,116.288 177.64,116.305 ; 177.19,121.507 177.521,118.294 177.64,116.305
  Top Layer w1: Q1.3 140.792,121.075 141.364,120.504 141.612,120.504 143.982,118.134 143.982,116.72
  Top Layer w1.5: 134.468,116.211 134.938,116.148 135.42,116.148 137.542,115.907 141.7,115.907 143.982,116.72 LED6.1
UDPI: pad.4 U2.19 | length 3.9
  Top Layer w0.25: U2.19@142.689,128.898 142.689,129.685 142.766,129.763 145.173,129.763 pad.4
VIB: R48.1 SW1.2 U2.11 | length 10.2
  Top Layer w0.25: U2.11 144.386,126.751 144.386,126.334 145.821,124.898 146.836,124.898 146.836,126.248 ; R48.1 147.683,126.811 147.12,126.248 146.836,126.248 ; SW1.2 147.361,123.511 146.888,123.984 146.888,126.195 146.836,126.248
"": U2.1 U2.2 U2.6 U2.7 U2.8 U2.10 U2.12 U2.13 U2.14 U2.15 U2.16 U2.17 U2.18 U2.20 U2.21

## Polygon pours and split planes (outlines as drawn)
GND on Top Layer (solid, pour order 4): 76.2,77.095 212.166,77.095 212.166,156.508 76.2,156.508
GND on Bottom Layer (solid, pour order 5): 77.009,76.2 212.976,76.2 212.976,155.613 77.009,155.613
2.5V on Top Layer (solid, remove dead copper, pour order 0): 135.585,128.175 135.585,124.873 136.865,124.873 137.119,125.127 139.903,125.127 140.157,125.381 140.157,127.437 139.725,127.869 138.962,127.869 138.506,127.413 137.998,127.413 137.871,127.54 137.871,128.302 137.744,128.429 135.839,128.429
GND on Bottom Layer (solid, remove dead copper, pour order 1): 131.688,122.2 149.677,122.2 149.695,122.218 149.695,130.2 131.688,130.2
GND on Top Layer (solid, remove dead copper, pour order 2): 131.713,130.188 131.713,122.188 149.575,122.188 149.72,122.333 149.72,130.188 131.832,130.188 131.818,130.202
GND on Top Layer (solid, remove dead copper, pour order 3): 131.78,130.202 131.775,130.207 131.813,130.207

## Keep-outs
Board Outline Layer:
  lines w0.1 net "": 79.004,115.638 79.004,120.138 102.891,120.138 ccw(c102.891,120.488) 103.204,120.332 ccw(c102.488,120.688) 103.276,120.554 ccw(c102.931,120.613) 103.137,120.896 83.812,134.936 86.457,138.577 105.782,124.536 ccw(c105.988,124.819) 106.15,124.509 ccw(c105.779,125.218) 106.339,124.647 ccw(c106.094,124.897) 106.427,125.005 99.045,147.722 103.325,149.113 110.707,126.395 ccw(c111.039,126.504) 110.988,126.157 ccw(c111.105,126.949) 111.222,126.157 ccw(c111.171,126.504) 111.504,126.395 118.885,149.113 123.165,147.722 115.783,125.005 ccw(c116.116,124.897) 115.871,124.647 ccw(c116.431,125.218) 116.06,124.509 ccw(c116.222,124.819) 116.428,124.536 135.753,138.577 138.398,134.936 119.849,121.459 ccw(c119.937,121.338) 119.937,121.188 138.406,121.188 ccw(c138.406,121.488) 138.706,121.488 138.706,121.888 ccw(c138.406,121.888) 138.406,122.188 132.006,122.188 cw(c132.006,122.488) 131.706,122.488 131.706,129.39 cw(c132.504,129.39) 132.504,130.188 148.908,130.188 cw(c148.908,129.39) 149.706,129.39 149.706,122.488 cw(c149.406,122.488) 149.406,122.188 143.006,122.188 ccw(c143.006,121.888) 142.706,121.888 142.706,121.488 ccw(c143.006,121.488) 143.006,121.188 161.475,121.188 ccw(c161.475,121.338) 161.564,121.459 143.014,134.936 145.659,138.577 164.984,124.536 ccw(c165.19,124.819) 165.352,124.509 ccw(c164.981,125.218) 165.541,124.647 ccw(c165.296,124.897) 165.629,125.005 158.247,147.722 162.527,149.113 169.908,126.395 ccw(c170.241,126.504) 170.19,126.157 ccw(c170.307,126.949) 170.424,126.157 ccw(c170.373,126.504) 170.706,126.395 178.087,149.113 182.367,147.722 174.985,125.005 ccw(c175.318,124.897) 175.073,124.647 ccw(c175.633,125.218) 175.262,124.509 ccw(c175.424,124.819) 175.63,124.536 194.955,138.577 197.6,134.936 178.275,120.896 ccw(c178.481,120.613) 178.136,120.554 ccw(c178.924,120.688) 178.208,120.332 ccw(c178.521,120.488) 178.521,120.138 202.408,120.138 202.408,115.638 178.521,115.638 ccw(c178.521,115.288) 178.208,115.443 ccw(c178.924,115.088) 178.136,115.221 ccw(c178.481,115.163) 178.275,114.88 197.6,100.84 194.955,97.199 175.63,111.239 ccw(c175.424,110.956) 175.262,111.266 ccw(c175.633,110.557) 175.073,111.129 ccw(c175.318,110.879) 174.985,110.771 182.367,88.053 178.087,86.663 170.706,109.38 ccw(c170.373,109.272) 170.424,109.618 ccw(c170.307,108.827) 170.19,109.618 ccw(c170.241,109.272) 169.908,109.38 162.527,86.663 158.247,88.053 165.629,110.771 ccw(c165.296,110.879) 165.541,111.129 ccw(c164.981,110.557) 165.352,111.266 ccw(c165.19,110.956) 164.984,111.239 145.659,97.199 143.014,100.84 161.701,114.416 ccw(c161.613,114.538) 161.613,114.688 119.799,114.688 ccw(c119.799,114.538) 119.711,114.416 138.398,100.84 135.753,97.199 116.428,111.239 ccw(c116.222,110.956) 116.06,111.266 ccw(c116.431,110.557) 115.871,111.129 ccw(c116.116,110.879) 115.783,110.771 123.165,88.053 118.885,86.663 111.504,109.38 ccw(c111.171,109.272) 111.222,109.618 ccw(c111.105,108.827) 110.988,109.618 ccw(c111.039,109.272) 110.707,109.38 103.325,86.663 99.045,88.053 106.427,110.771 ccw(c106.094,110.879) 106.339,111.129 ccw(c105.779,110.557) 106.15,111.266 ccw(c105.988,110.956) 105.782,111.239 86.457,97.199 83.812,100.84 103.137,114.88 ccw(c102.931,115.163) 103.276,115.221 ccw(c102.488,115.088) 103.204,115.443 ccw(c102.891,115.288) 102.891,115.638 79.004,115.638

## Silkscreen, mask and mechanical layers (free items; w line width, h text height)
Top Silkscreen Layer:
  text "-" at 169.11,122.449 h1.99 r18
  text "-" at 172.551,122.36 h1.99 r18
  text "+" at 109.222,121.823 h1.99 r18
  text "+" at 113.458,121.788 h1.99 r18
  text "-" at 166.62,121.052 h1.99 r18
  text "-" at 174.278,121.014 h1.99 r18
  text "+" at 106.406,119.109 h1.99 r18
  text "+" at 115.566,118.969 h1.99 r18
  text "-" at 165.681,117.343 h1.99 r18
  text "-" at 174.405,117.343 h1.99 r18
  text "bukajlag" at 113.955,117.036 h1.3
  text "+" at 105.779,115.856 h1.99 r18
  text "2024" at 117.904,115.296 h1.3
  text "robotfuze.com" at 145.908,114.982 h0.97
  text "+" at 115.927,114.949 h1.99 r18
  text "-" at 173.555,114.664 h1.99 r18
  text "-" at 165.655,112.936 h1.99 r18
  text "+" at 107.349,112.263 h1.99 r18
  text "-" at 170.634,112.2 h1.99 r18
  text "+" at 114.514,111.943 h1.99 r18
  text "+" at 109.863,111.212 h1.99 r18
Mech3:
  region net "": 131.912,122.282 132.006,122.188 147.035,122.188 147.244,122.396 147.244,125.254 147.676,125.686 149.403,125.686 149.441,125.724 149.441,129.673 149.141,129.973 132.253,129.973 131.928,129.648 131.928,122.295 131.94,122.282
